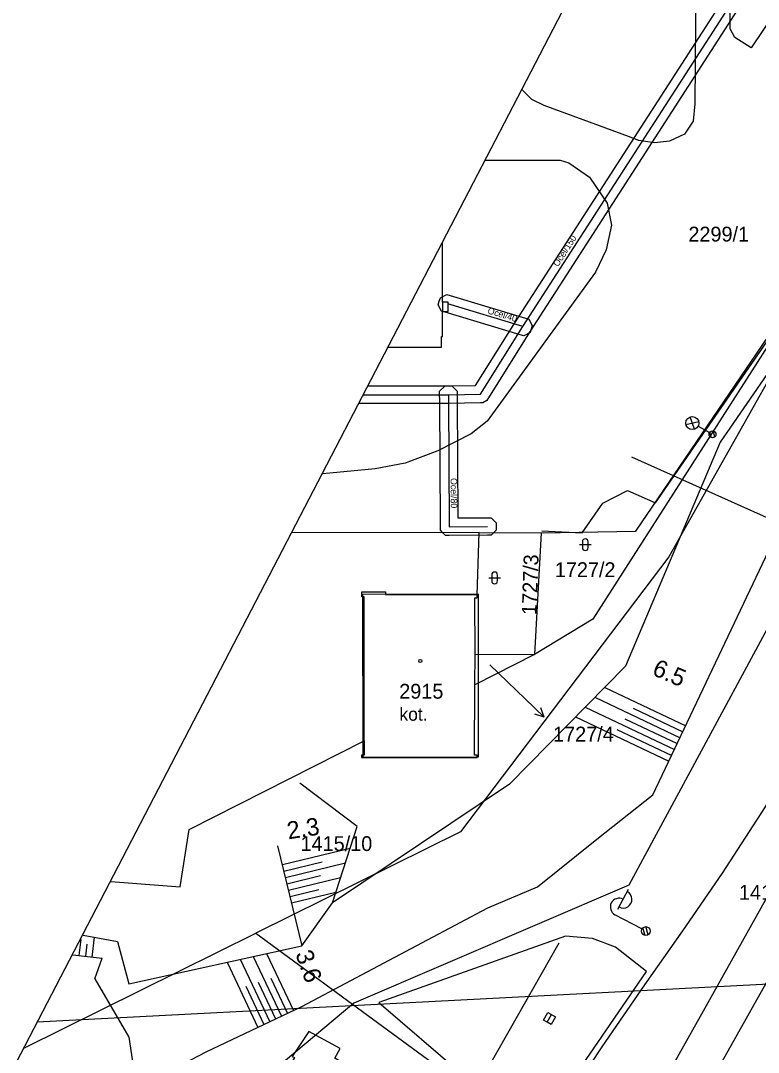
# Model space of a CAD drawing. Extents: x -781083 to -763634, y -1029516 to -1022695.
# Drawn here: x -765146.9 to -765062.3, y -1023999.1 to -1023880.9 of the extents above; entities that cross this region are included whole.
import ezdxf

# ---------------------------------------------------------------- set-up
doc = ezdxf.new("R2010")
doc.units = 0
for name, color, linetype in [('GasNet_ochr. pásmo', 7, 'Continuous'), ('GasNet_plyn STL', 7, 'Continuous'), ('Hranice parcel', 7, 'Continuous'), ('Parcelní čísla', 7, 'Continuous'), ('Pop  PČ popisy', 7, 'Continuous'), ('SO128602_NN_trasa', 7, 'Continuous'), ('SVAS_kanalizace', 7, 'Continuous'), ('Vnitřní kresba', 7, 'Continuous'), ('Vodafone_ vzduch', 7, 'Continuous'), ('Vrstva 1', 7, 'Continuous'), ('Vrstva 16', 7, 'Continuous'), ('Vrstva 17', 7, 'Continuous'), ('Vrstva 23', 7, 'Continuous'), ('Vrstva 25', 7, 'Continuous'), ('Vrstva 43', 7, 'Continuous'), ('Vrstva 48', 7, 'Continuous'), ('Vrstva 49', 7, 'Continuous'), ('Vrstva 51', 7, 'Continuous'), ('Značky budov', 7, 'Continuous'), ('Značky kultur', 7, 'Continuous')]:
    doc.layers.add(name, color=color, linetype=linetype)

# ---------------------------------------------------------------- blocks, each defined once
blk = doc.blocks.new('4.02')
at = {"layer": 'Značky budov'}
blk.add_circle((-0.1, 0), 1.75, dxfattribs=at)
blk = doc.blocks.new('3.16')
at = {"layer": 'Značky kultur'}
for p, q in [((-6.7, 6.7), (6.7, 6.7)), ((-3.3, 10.1), (-3.3, 3.3)), ((3.3, 3.3), (3.3, 10.1))]:
    blk.add_line(p, q, dxfattribs=at)
for centre, start, end in [((0, 10), 0, 180), ((0, 3.3), 180, 359.9879)]:
    blk.add_arc(centre, 3.35, start, end, dxfattribs=at)
blk = doc.blocks.new('C669_6')
at = {"layer": 'Vrstva 25'}
for p, q in [((0, 5), (0, 40)), ((7, 40), (33, 40)), ((-4.8, -1.5), (1.4, 4.8)), ((-2.4, -4.4), (4.4, 2.4))]:
    blk.add_line(p, q, dxfattribs=at)
blk.add_circle((0, 0), 5, dxfattribs=at)
blk.add_circle((0, 0), 5, dxfattribs=at)
for centre, start, end in [((10, 40), 0, 180), ((20, 39.9), 179.2974, 0.7026)]:
    blk.add_arc(centre, 10, start, end, dxfattribs=at)
blk = doc.blocks.new('C187_6')
at = {"layer": 'Vrstva 25'}
for p, q in [((-4.9, 32.1), (5, 20.9)), ((-4.8, 20.8), (5.1, 32)), ((0, 19), (0, 4)), ((-3.9, -0.8), (0.8, 3.9)), ((-1.2, -3.8), (3.8, 1.2))]:
    blk.add_line(p, q, dxfattribs=at)
for centre, radius in [((0, 26.5), 7.49), ((0, 0), 4), ((0, 0), 4)]:
    blk.add_circle(centre, radius, dxfattribs=at)
blk = doc.blocks.new('C154_1')
at = {"layer": 'Vrstva 43'}
blk.add_lwpolyline([(-5, 0), (-5, 5), (5, 5), (5, -5), (-5, -5), (-5, 0), (5, 0)], dxfattribs=at)

msp = doc.modelspace()

# ---------------------------------------------------------------- linework, layer by layer
msp.add_lwpolyline([(-765336.12, -1024363.48), (-765204.05, -1024432.09), (-764769.73, -1023596.11), (-764901.79, -1023527.49)], close=True)
at = {"layer": 'GasNet_ochr. pásmo'}
msp.add_lwpolyline([(-765107.14, -1023922.75), (-765097.87, -1023922.75), (-765094.74, -1023922.69), (-765090.17, -1023915.41), (-765066.03, -1023877.96), (-765059.44, -1023867.88), (-765059.21, -1023867.54), (-765058.4, -1023867.37), (-765058.05, -1023867.59), (-765057.71, -1023867.82), (-765057.54, -1023868.63), (-765057.76, -1023868.98), (-765064.35, -1023879.05), (-765088.48, -1023916.48), (-765093.33, -1023924.21), (-765093.46, -1023924.42), (-765093.91, -1023924.67), (-765094.16, -1023924.68), (-765097.85, -1023924.75), (-765108.18, -1023924.75)], dxfattribs=at)
for points in [[(-765089.22, -1023917.02), (-765089.62, -1023916.9), (-765098.23, -1023914.3), (-765098.63, -1023914.18), (-765099.02, -1023913.45), (-765098.9, -1023913.05), (-765098.78, -1023912.65), (-765098.05, -1023912.26), (-765097.65, -1023912.38), (-765089.04, -1023914.99), (-765088.64, -1023915.11), (-765088.25, -1023915.84), (-765088.37, -1023916.24), (-765088.49, -1023916.63)], [(-765096.85, -1023924.43), (-765096.79, -1023937.88), (-765093.39, -1023937.87), (-765092.97, -1023937.87), (-765092.39, -1023938.45), (-765092.39, -1023938.86), (-765092.39, -1023939.28), (-765092.97, -1023939.87), (-765093.38, -1023939.87), (-765097.78, -1023939.88), (-765098.2, -1023939.88), (-765098.49, -1023939.59), (-765098.78, -1023939.29), (-765098.78, -1023938.88), (-765098.78, -1023938.67), (-765098.85, -1023924.43), (-765098.85, -1023924.36), (-765098.86, -1023923.76), (-765098.86, -1023923.34), (-765098.28, -1023922.76), (-765097.86, -1023922.75), (-765097.45, -1023922.75), (-765096.86, -1023923.33), (-765096.86, -1023923.75), (-765096.85, -1023924.36)]]:
    msp.add_lwpolyline(points, close=True, dxfattribs=at)
at = {"layer": 'GasNet_plyn STL'}
msp.add_line((-765089.33, -1023915.95), (-765097.94, -1023913.34), dxfattribs=at)
for points in [[(-765107.66, -1023923.75), (-765097.86, -1023923.75), (-765094.18, -1023923.68), (-765089.33, -1023915.95), (-765065.19, -1023878.51), (-765058.6, -1023868.43)], [(-765097.86, -1023923.75), (-765097.85, -1023924.36), (-765097.85, -1023924.43), (-765097.78, -1023938.67), (-765097.78, -1023938.88), (-765093.39, -1023938.87)]]:
    msp.add_lwpolyline(points, dxfattribs=at)
at = {"layer": 'Hranice parcel'}
for p, q in [((-765094.56, -1023946.69), (-765094.32, -1023939.54)), ((-765094.32, -1023939.54), (-765087.24, -1023939.58)), ((-765087.24, -1023939.58), (-765087.99, -1023953.53)), ((-765094.81, -1023956.99), (-765094.78, -1023953.49)), ((-765087.99, -1023953.53), (-765094.81, -1023956.99)), ((-765094.78, -1023953.49), (-765087.99, -1023953.53)), ((-765146.45, -1023998.61), (-765119.92, -1023985.47))]:
    msp.add_line(p, q, dxfattribs=at)
for points in [[(-765069.41, -1023867.26), (-765069.63, -1023890.41), (-765069.8, -1023892.4), (-765070.79, -1023893.89), (-765072.51, -1023894.68), (-765074.22, -1023894.9), (-765076.05, -1023894.63), (-765077.22, -1023894.18), (-765086.89, -1023890.62), (-765088.28, -1023889.92), (-765089.35, -1023888.87), (-765089.39, -1023888.78)], [(-765055.85, -1023873.1), (-765063.15, -1023883.99), (-765065.04, -1023882.8), (-765065.56, -1023881.82), (-765065.57, -1023867.35)], [(-765036.72, -1023885.86), (-765036.68, -1023886.39), (-765051.33, -1023904.59), (-765072.6, -1023942.32), (-765096.48, -1023973.87), (-765119.92, -1023985.47)], [(-765093.6, -1023896.88), (-765085.05, -1023896.88), (-765084.07, -1023897.18), (-765081.68, -1023898.84), (-765079.65, -1023901.81), (-765079.18, -1023904.34), (-765079.76, -1023907.16), (-765081, -1023909.71), (-765093.41, -1023926.78), (-765095.26, -1023928.22), (-765099.05, -1023930.17), (-765102.8, -1023931.59), (-765106.25, -1023932.24), (-765112.26, -1023932.81)], [(-765050.44, -1023901.27), (-765081.31, -1023949.46), (-765087.99, -1023953.53)], [(-765087.24, -1023939.58), (-765076.36, -1023939.4), (-765050.44, -1023901.27)], [(-765098.64, -1023918.29), (-765098.64, -1023917.09), (-765098.54, -1023917.09), (-765098.54, -1023914.22), (-765097.89, -1023914.22), (-765097.89, -1023913.15), (-765098.54, -1023913.15), (-765098.53, -1023906.38)], [(-765104.72, -1023918.29), (-765098.64, -1023918.29)], [(-765094.32, -1023939.54), (-765115.79, -1023939.6)], [(-765107.53, -1023963.44), (-765107.53, -1023946.93), (-765107.78, -1023946.93), (-765107.78, -1023946.63), (-765107.78, -1023946.33), (-765105.06, -1023946.34), (-765105.07, -1023946.64), (-765094.56, -1023946.69)], [(-765094.78, -1023953.49), (-765094.81, -1023947.03), (-765094.56, -1023947.03), (-765094.56, -1023946.69)], [(-765107.53, -1023963.44), (-765107.53, -1023965.05), (-765107.83, -1023965.05), (-765107.83, -1023965.13), (-765107.83, -1023965.35), (-765094.57, -1023965.35), (-765094.57, -1023965.05), (-765094.87, -1023965.05), (-765094.81, -1023956.99)], [(-765136.55, -1023979.56), (-765128.6, -1023980.14), (-765127.58, -1023973.6), (-765107.53, -1023963.44)], [(-765119.92, -1023985.47), (-765108.85, -1023993.6), (-765095.68, -1024003.27), (-765105.7, -1024021.16)], [(-765115.75, -1023999.6), (-765115.49, -1023999.72), (-765120.16, -1024007.73), (-765120.35, -1024007.62), (-765123.72, -1024013.68), (-765114.2, -1024019.12), (-765109.59, -1024011.19), (-765107.69, -1024012.3), (-765104.24, -1024006.04), (-765107.77, -1024004.12), (-765106.72, -1024002.26), (-765110.88, -1023999.8), (-765110.26, -1023998.68), (-765113.84, -1023996.73), (-765115.75, -1023999.6)]]:
    msp.add_lwpolyline(points, dxfattribs=at)
at = {"layer": 'Pop  PČ popisy'}
for p, q in [((-765093.11, -1023954.71), (-765089.05, -1023958.62)), ((-765089.05, -1023958.62), (-765086.89, -1023960.71)), ((-765086.89, -1023960.71), (-765087.26, -1023959.65)), ((-765086.89, -1023960.71), (-765087.96, -1023960.37))]:
    msp.add_line(p, q, dxfattribs=at)
at = {"layer": 'SO128602_NN_trasa'}
msp.add_lwpolyline([(-765111.62, -1024019.29), (-765109.87, -1024016.2), (-765103.92, -1024019.58), (-765085.17, -1023986.56)], dxfattribs=at)
at = {"layer": 'SVAS_kanalizace'}
msp.add_lwpolyline([(-765076.86, -1023930.89), (-765058.47, -1023939.14), (-765034.4, -1023949.94), (-765017.31, -1023957.61), (-765002.1, -1023964.44), (-764989.15, -1023970.25)], dxfattribs=at)
at = {"layer": 'Vnitřní kresba'}
for p, q in [((-765098.54, -1023913.15), (-765098.54, -1023914.22)), ((-765105.07, -1023946.64), (-765107.78, -1023946.63))]:
    msp.add_line(p, q, dxfattribs=at)
at = {"layer": 'Vodafone_ vzduch'}
msp.add_line((-765145, -1023995.63), (-765022.19, -1023989.27), dxfattribs=at)
at = {"layer": 'Vrstva 1'}
for points in [[(-765066.82, -1024000.8), (-765059.52, -1023987.8), (-765051.08, -1023972.75), (-765042.31, -1023957.11), (-765034.53, -1023943.23), (-765024.84, -1023926.01), (-765014.6, -1023907.75), (-765007.2, -1023894.56), (-765001.3, -1023884.06), (-764995.86, -1023874.38), (-764990.29, -1023864.42), (-764985.5, -1023855.89), (-764983.13, -1023851.68), (-764978.13, -1023842.8), (-764973.49, -1023834.78), (-764970.63, -1023830.05), (-764962.15, -1023815.84)], [(-765076.99, -1024009.25), (-765068.63, -1023994.36), (-765060.96, -1023980.67), (-765051.42, -1023963.64), (-765043.39, -1023949.3), (-765036.09, -1023936.27), (-765028.08, -1023922), (-765021.19, -1023909.71), (-765014.1, -1023897.06), (-765011.26, -1023891.99), (-765007.44, -1023885.16), (-765001.64, -1023874.77), (-764998.25, -1023868.71), (-764992.69, -1023859.11), (-764988.39, -1023852.18), (-764986.76, -1023849.67), (-764979.19, -1023837.99)], [(-765084.18, -1024004.45), (-765080.24, -1023998.48), (-765075.34, -1023991.39), (-765070.99, -1023985.18), (-765066.45, -1023978.59), (-765061.6, -1023971.11), (-765056.12, -1023961.81), (-765053.82, -1023957.76), (-765048.17, -1023947.72), (-765040.08, -1023933.36), (-765032.25, -1023919.48), (-765024.77, -1023906.18), (-765015.35, -1023889.54), (-765011.12, -1023882.03), (-765006.79, -1023874.58)]]:
    msp.add_lwpolyline(points, dxfattribs=at)
at = {"layer": 'Vrstva 16'}
msp.add_lwpolyline([(-765122.17, -1024068.88), (-765117.92, -1024061.52), (-765111.49, -1024050.06), (-765094.8, -1024020.16), (-765087.65, -1024008.38), (-765082.98, -1024001.3), (-765075.14, -1023989.84), (-765078.7, -1023987.07), (-765081.36, -1023986.07), (-765084.44, -1023985.8), (-765105.83, -1023993.43), (-765096.3, -1024001.6), (-765107.34, -1024020.04)], dxfattribs=at)
at = {"layer": 'Vrstva 17'}
msp.add_lwpolyline([(-764984.37, -1023833.78), (-764994.21, -1023847.8), (-765035.2, -1023902.66), (-765053.31, -1023935.71), (-765077.19, -1023979.95), (-765108.69, -1023993.47), (-765147.86, -1024026.34)], dxfattribs=at)
at = {"layer": 'Vrstva 23'}
for points in [[(-765094.46, -1023946.62), (-765107.71, -1023946.64), (-765107.65, -1023965.32)], [(-765094.46, -1023946.62), (-765094.43, -1023965.28), (-765107.65, -1023965.32)]]:
    msp.add_lwpolyline(points, dxfattribs=at)
at = {"layer": 'Vrstva 48'}
for p, q in [((-765079.94, -1023957.3), (-765070.66, -1023961.71)), ((-765081.06, -1023958.43), (-765071.3, -1023963.06)), ((-765082.17, -1023959.56), (-765071.94, -1023964.42)), ((-765076.69, -1023959.67), (-765070.98, -1023962.38)), ((-765083.29, -1023960.69), (-765072.58, -1023965.77)), ((-765077.62, -1023960.89), (-765071.62, -1023963.74)), ((-765078.54, -1023962.11), (-765072.26, -1023965.09)), ((-765109.13, -1023975.76), (-765116.89, -1023977.65)), ((-765112.33, -1023977.31), (-765116.72, -1023978.38)), ((-765109.67, -1023977.44), (-765116.54, -1023979.11)), ((-765112.51, -1023978.9), (-765116.36, -1023979.84)), ((-765110.21, -1023979.11), (-765116.19, -1023980.57)), ((-765112.69, -1023980.49), (-765116.01, -1023981.29)), ((-765110.75, -1023980.79), (-765115.83, -1023982.02)), ((-765140, -1023986.2), (-765140.21, -1023988.04)), ((-765139.3, -1023986.72), (-765139.46, -1023988.12)), ((-765138.46, -1023985.92), (-765138.72, -1023988.21)), ((-765118.72, -1023987.8), (-765115.62, -1023994.33)), ((-765123.23, -1023988.79), (-765119.69, -1023996.26)), ((-765121.73, -1023988.46), (-765118.33, -1023995.62)), ((-765120.23, -1023988.13), (-765116.98, -1023994.98)), ((-765121.09, -1023991.55), (-765119.01, -1023995.94)), ((-765119.65, -1023991.1), (-765117.66, -1023995.3)), ((-765118.21, -1023990.64), (-765116.3, -1023994.66))]:
    msp.add_line(p, q, dxfattribs=at)
at = {"layer": 'Vrstva 49'}
for points in [[(-765029.57, -1023877.26), (-765040.04, -1023890.55), (-765066.72, -1023929.18), (-765077.55, -1023954.87), (-765090.87, -1023968.38), (-765111.14, -1023982)], [(-765134.47, -1023997.37), (-765133.61, -1024003.22), (-765125.55, -1023999.04), (-765114.65, -1023993.87), (-765093.33, -1023982.55), (-765087.64, -1023980.17), (-765080.86, -1023974.68), (-765074.41, -1023969.61), (-765056.8, -1023932.51), (-765038.54, -1023902.67), (-765026.59, -1023885.36)], [(-765111.14, -1023982), (-765108.31, -1023973.24), (-765114.87, -1023968.27)], [(-765117.43, -1023975.46), (-765114.64, -1023986.91)], [(-765139.73, -1023985.68), (-765135.79, -1023986.43), (-765134.49, -1023991.26), (-765114.64, -1023986.91), (-765111.14, -1023982)], [(-765140.92, -1023987.96), (-765137.55, -1023988.34)], [(-765138.39, -1023990.7), (-765137.55, -1023988.34)], [(-765138.39, -1023990.7), (-765134.47, -1023997.37)]]:
    msp.add_lwpolyline(points, dxfattribs=at)
at = {"layer": 'Vrstva 51'}
msp.add_lwpolyline([(-765087.15, -1023939.36), (-765082.51, -1023939.6), (-765080.15, -1023936.17), (-765077.34, -1023934.72), (-765074.14, -1023936.15), (-765068.31, -1023927.73), (-765041.8, -1023889.43), (-765042.44, -1023876.74), (-765031.84, -1023872.54)], dxfattribs=at)

# ---------------------------------------------------------------- block references
at = {"layer": 'Vrstva 25', "xscale": 0.1}
for name, p, yscale, rotation in [('C187_6', (-765067.59, -1023928.3), 0.10000000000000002, 60.73795128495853), ('C669_6', (-765075.23, -1023985.22), 0.09999999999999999, 62.156625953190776)]:
    msp.add_blockref(name, p, dxfattribs=dict(at, yscale=yscale, rotation=rotation))
at = {"layer": 'Vrstva 43', "xscale": 0.10000000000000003, "yscale": 0.10000000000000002, "rotation": 60.73328616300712}
msp.add_blockref('C154_1', (-765086.28, -1023995.24), dxfattribs=at)
at = {"layer": 'Značky budov', "xscale": 0.1, "yscale": 0.10000000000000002}
msp.add_blockref('4.02', (-765101.07, -1023954.28), dxfattribs=at)
at = {"layer": 'Značky kultur', "xscale": 0.1, "yscale": 0.10000000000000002}
for p in [(-765082.17, -1023941.61), (-765092.56, -1023945.42)]:
    msp.add_blockref('3.16', p, dxfattribs=at)

# ---------------------------------------------------------------- texts
at = {"layer": 'GasNet_plyn STL'}
for s, rotation, p in [('Ocel/150', 57.1861, (-765085.29, -1023909.15)), ('Ocel/40', 343.1636, (-765093.43, -1023914.43)), ('Ocel/80', 270.2817, (-765097.6, -1023933.31))]:
    msp.add_text(s, height=0.75, rotation=rotation, dxfattribs=at).set_placement(p)
at = {"layer": 'Parcelní čísla'}
for s, p in [('2299/1', (-765070.35, -1023906.2)), ('1727/2', (-765085.66, -1023944.66)), ('2915', (-765103.49, -1023958.59)), ('1727/4', (-765085.86, -1023963.5)), ('1415/10', (-765114.8, -1023976.05)), ('1415/1', (-765064.56, -1023981.64))]:
    msp.add_text(s, height=1.7, dxfattribs=at).set_placement(p)
msp.add_text('1727/3', height=1.7, rotation=88, dxfattribs=at).set_placement((-765087.76, -1023949.03))
at = {"layer": 'Vrstva 23'}
msp.add_text('kot.', height=1.5, rotation=0.0921, dxfattribs=at).set_placement((-765103.47, -1023961.12))
at = {"layer": 'Vrstva 48'}
for s, rotation, p in [('6.5', 336.5268, (-765074.62, -1023955.81)), ('2.3', 8.657, (-765116.2, -1023974.72)), ('3.6', 289.7507, (-765115.42, -1023987.83))]:
    msp.add_text(s, height=2, rotation=rotation, dxfattribs=at).set_placement(p)

doc.saveas('drawing.dxf')
